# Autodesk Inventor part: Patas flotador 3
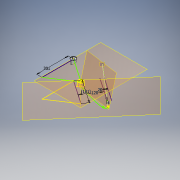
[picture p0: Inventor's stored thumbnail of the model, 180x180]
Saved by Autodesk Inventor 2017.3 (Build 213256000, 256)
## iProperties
Part Number: Patas flotador 3
Material: Genérico
Document SubType Name: Modeling
Designer: PABLO HERNANDEZ
Density: 1 g/cm^3
Appearance: Valor por defecto
Author: PABLO HERNANDEZ
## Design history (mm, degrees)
node "Geometría reparada1"
sketch "Boceto1"
  geometry: C1 r 16 at (0, 0); 1 further point
  constraints: 1 centre point, 1 coincident
  dimensions: "d0" = 32 diameter of C1
extrude "Extrusión1" new body sketch "Boceto1" distance "d1" = 1; taper "d2" = 0 deg; dims "d93" = 1, "d94" = 0
sketch "Boceto2"
  geometry: C1 r 16 at (0, 0); C2 r 15 at (0, 0); C3 r 14 at (0, 0); 1 further point
  constraints: 3 centre point, 1 coincident
  dimensions: "d3" = 1 radial gap between concentric circles of C1 C2; "d4" = 1 radial gap between concentric circles of C2 C3
extrude "Extrusión2" join sketch "Boceto2" distance "d5" = 3; taper "d6" = 0 deg
sketch "Boceto3"
  geometry: C1 r 15 at (0, 0); C2 r 14 at (0, 0); 1 further point
  constraints: 2 centre point, 1 coincident
  dimensions: "d7" = 1 radial gap between concentric circles of C1 C2; "d123" = 30 diameter of C1
extrude "Extrusión3" join sketch "Boceto3" distance "d8" = 2; taper "d9" = 0 deg
sketch "Boceto4"
  geometry: C1 r 16 at (0, 0); 1 further point
  constraints: 1 centre point, 1 coincident
extrude "Extrusión4" cut sketch "Boceto4" distance "d10" = 0.5; taper "d11" = 0 deg
sketch "Boceto7"
  geometry: L1 (1.5, -15.93)-(1.5, 15.93); L2 (-1.5, -15.93)-(-1.5, 15.93); A1 r 16 centre (0, 0) between (1.5, 15.93) and (-1.5, 15.93); A2 r 16 centre (0, 0) between (-1.5, -15.93) and (1.5, -15.93); 2 further points
  constraints: 4 end point, 4 point on circle, 2 centre point, 1 coincident
extrude "Extrusión7" join sketch "Boceto7" distance "d63" = 25; taper "d64" = 0 deg
fillet "Empalme1" dims "d71" = 2
fillet "Empalme2" dims "d95" = 3
fillet "Empalme3" dims "d96" = 0.5
sketch "Boceto12"
  geometry: C1 r 1.2 at (-6, 0); C2 r 1.2 at (6, 0); 2 further points
  constraints: 2 centre point, 1 coincident
  dimensions: "d104" = 6 distance of point (0, 0) point (-6, 0); "d114" = 2.4 diameter of C1; "d115" = 2.4 diameter of C2
extrude "Extrusión9" cut sketch "Boceto12" stored distance "d116" = 10; taper "d117" = 0 deg
sketch "Boceto13"
  geometry: C1 r 1.2 at (-6, 0) reference; C2 r 1.75 at (-6, 0); C3 r 1.2 at (6, 0) reference; C4 r 1.75 at (6, 0); 1 further point
  constraints: 2 centre point, 2 coincident
  dimensions: "d118" = 3.5 diameter of C2; "d119" = 3.5 diameter of C4
extrude "Extrusión10" join sketch "Boceto13" distance "d120" = 3; taper "d121" = 0 deg
fillet "Empalme4" dims "d122" = 1
sketch "Boceto14"
  geometry: 1 further point
sketch "Boceto15"
  geometry: C1 r 1.2 at (6, 0) reference; C2 r 2.5 at (6, 0); C3 r 1.2 at (-6, 0) reference; C4 r 2.5 at (-6, 0); 1 further point
  constraints: 2 centre point, 2 coincident
  dimensions: "d124" = 5 diameter of C2; "d125" = 5 diameter of C4
extrude "Extrusión11" cut sketch "Boceto15" distance "d126" = 10; taper "d127" = 0 deg
sketch "Boceto16"
  geometry: L1 (0, 0)-(0, -201); L2 (0, -201)-(149.324, -102.291); L3 (0, 0)-(149.324, -102.291); 1 further point
  constraints: 6 end point, 2 coincident, 1 vertical
  dimensions: "d130" = 201 distance of L1.start L1.end
node "Plano de trabajo1"
node "Plano de trabajo4"
node "Plano de trabajo5"
sketch "Boceto21"
  geometry: C1 r 2 at (0, 0); 1 further point
  constraints: 1 centre point
  dimensions: "d140" = 4 diameter of C1
sketch "Boceto23"
  geometry: 1 further point
sketch "Boceto24"
  geometry: C1 r 2 at (0, 0); 1 further point
  constraints: 1 centre point
node "Eje de trabajo1"
feature "Desplazar cuerpo2"
feature "Desplazar cuerpo3"
node "Plano de trabajo6"
sketch "Boceto26"
  geometry: 2 further points
node "Plano de trabajo7"
sketch "Boceto28"
  geometry: L1 (154.995, 0)-(83.073, 325.592) reference; 3 further points
  constraints: 3 other
node "Plano de trabajo8"
sketch "Boceto29"
  geometry: C1 r 2 at (0, 0); 1 further point
  constraints: 1 centre point
  dimensions: "d161" = 4 diameter of C1
extrude "Extrusión14" join sketch "Boceto29" stored distance "d162" = 0; taper "d163" = 0 deg
node "Plano de trabajo9"
sketch "Boceto30"
  geometry: C1 r 2 at (0, 0) reference; 1 further point
sketch "Boceto31"
  geometry: L1 (29.664, -3.107)-(0, 0) reference; L2 (29.849, 0)-(0, 0) reference; L3 (0, -3)-(29.849, -3) reference; A1 r 16 centre (15.93, -1.5) between (0, 0) and (0, -3) reference; A2 r 14 centre (15.93, -1.5) between (29.849, -3) and (29.849, 0) reference; 1 further point
node "Sólido1"
sketch "Boceto22"
  geometry: L1 (0, 0)-(0, -201) reference; L2 (0, -201)-(149.324, -102.291) reference; L3 (149.324, -102.291)-(0, 0); L4 (217.029, -3.215)-(67.705, 99.076); L5 (228.332, 13.284)-(79.008, 115.575); L6 (252.725, -33.938)-(0, 183.576); 1 further point
  constraints: 8 end point, 4 point on line, 2 parallel
  dimensions: "d157" = 120 distance between parallel lines of L4 L3; "d158" = 181 distance of L2.end L1.start (derived); "d160" = 20 distance between parallel lines of L4 L5
feature "Compuesta1"
node "Sup2"
other parameters: "sa_0" = 4, "d153" = 149.324, "d154" = -102.291, "d155" = 0, "d156" = -9.86699
